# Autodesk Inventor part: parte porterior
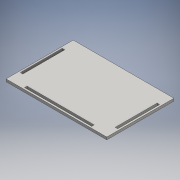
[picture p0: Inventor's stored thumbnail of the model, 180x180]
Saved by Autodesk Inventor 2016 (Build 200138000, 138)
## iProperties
Created: 2016-06
Part Number: parte porterior
Material: Genérico
Document SubType Name: Modeling
Designer: adm
Density: 1 g/cm^3
Appearance: Valor por defecto
Author: adm
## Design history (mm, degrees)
sketch "Boceto1"
  geometry: 1 further point
sketch "Boceto2"
  geometry: L1 (-60, -40)-(60, -40); L2 (60, -40)-(60, 40); L3 (60, 40)-(-60, 40); L4 (-60, 40)-(-60, -40); L5 (-60, -40)-(60, 40); L6 (60, -40)-(-60, 40); L7 (58, 25)-(58, -25); L8 (-58, -25)-(-58, 25); L9 (-55, 25)-(-55, -25); L10 (-58, -25)-(-55, -25); L11 (-58, 25)-(-55, 25); L12 (55, 25)-(58, 25); L13 (55, -25)-(58, -25); L14 (55, 25)-(55, -25); 3 further points
  constraints: 28 end point, 3 parallel, 2 midpoint, 2 perpendicular, 1 horizontal, 1 point on line, 1 vertical
  dimensions: "d0" = 120 distance of L3.end L2.end; "d1" = 80 distance of L2.end L1.end; "d2" = 2 distance between parallel lines of L2 L7; "d15" = 50 distance between parallel lines of L13 L12; "d16" = 50 distance between parallel lines of L10 L11; "d17" = 15 distance between parallel lines of L12 L3; "d18" = 15 distance between parallel lines of L11 L3
extrude "Extrusión1" new body sketch "Boceto2" distance "d7" = 3; taper "d8" = 0 deg
sketch "Boceto3"
  geometry: L1 (-60, -40)-(60, -40) reference; L2 (-40, -58)-(40, -58); L3 (-40, -55)-(40, -55); L4 (0, -55)-(0, -40); L5 (-40, -55)-(-40, -58); L6 (40, -55)-(40, -58); 1 further point
  constraints: 10 end point, 3 parallel, 2 midpoint, 1 vertical
  dimensions: "d10" = 3 distance between parallel lines of L2 L3; "d11" = 40 distance between parallel lines of L4 L5; "d12" = 40 distance between parallel lines of L6 L4
extrude "Extrusión2" cut sketch "Boceto3" distance "d13" = 10; taper "d14" = 0 deg
sketch "Boceto4"
  geometry: L1 (-40, -38)-(40, -38); L2 (-40, -35)-(40, -35); L3 (-40, -35)-(-40, -38); L4 (40, -35)-(40, -38); 1 further point
  constraints: 8 end point, 1 parallel
  dimensions: "d20" = 3 distance between parallel lines of L1 L2
extrude "Extrusión3" cut sketch "Boceto4" distance "d23" = 10; taper "d24" = 0 deg
node "Sólido1"
other parameters: "d3" = 3, "d4" = 3
